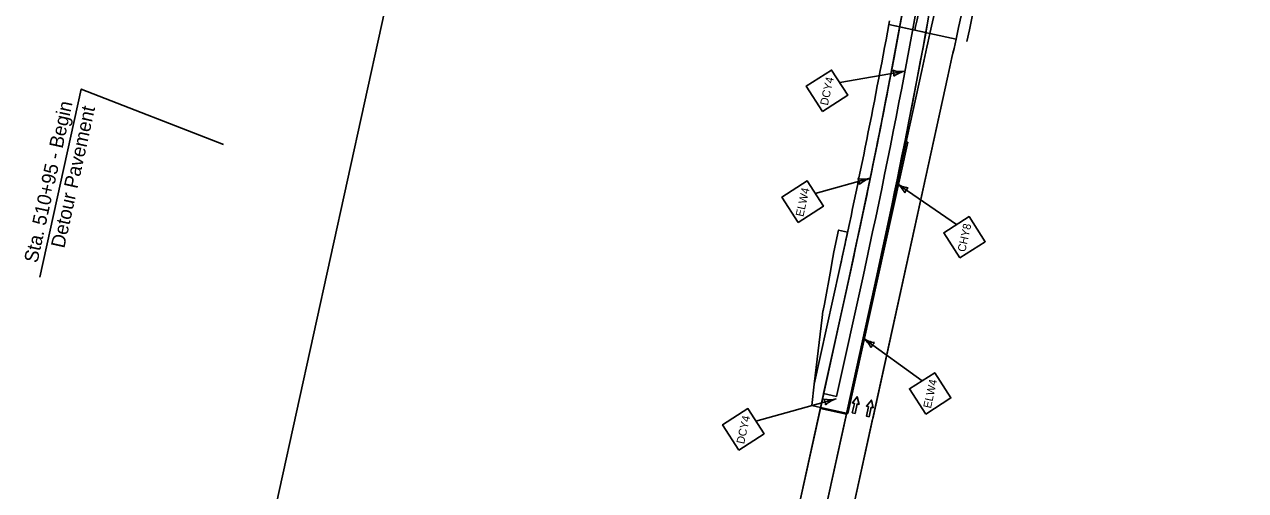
# Model space of a CAD drawing. Extents: x 14104283 to 14129344, y 8637090 to 8673339.
# Drawn here: x 14107065 to 14108164, y 8638989 to 8639409 of the extents above; entities that cross this region are included whole.
import ezdxf

# ---------------------------------------------------------------- set-up
doc = ezdxf.new("R2010")
doc.units = 0
for name, color, linetype in [('Cell', 7, 'Continuous'), ('Default', 7, 'Continuous'), ('dsn_stg_shd_prev', 7, 'Continuous'), ('dsnNonPlotable', 7, 'Continuous'), ('dsnPaintExistingEdgeLineRightWhite', 7, 'Continuous'), ('dsnPaintPlaceBrokenLineWhite', 7, 'Continuous'), ('dsnPaintPlaceChannelizingLaneYellow', 7, 'Continuous'), ('dsnPaintPlaceEdgeLineRightWhite', 7, 'Continuous'), ('dsnStdLabel', 7, 'Continuous'), ('dsnStgShadingPrevPav', 7, 'Continuous'), ('dsnTextOverlapOdd', 7, 'Continuous'), ('EdgePaved', 7, 'Continuous'), ('Level 2', 7, 'Continuous')]:
    doc.layers.add(name, color=color, linetype=linetype)

msp = doc.modelspace()

# ---------------------------------------------------------------- linework, layer by layer
at = {"layer": 'Cell'}
for points in [[(14107812.7, 8639058.7), (14107810.2, 8639059.2), (14107812.1, 8639067.7), (14107810.3, 8639068.1), (14107814.6, 8639073.6), (14107816.4, 8639066.8), (14107814.5, 8639067.2)], [(14107825.4, 8639055.7), (14107823, 8639056.2), (14107824.8, 8639064.8), (14107823, 8639065.2), (14107827.4, 8639070.6), (14107829.1, 8639063.8), (14107827.3, 8639064.2)]]:
    msp.add_lwpolyline(points, close=True, dxfattribs=at)
for points in [[(14107814.5, 8639067.2), (14107816.4, 8639066.8), (14107814.6, 8639073.6), (14107810.3, 8639068.1), (14107812.1, 8639067.7), (14107810.2, 8639059.2), (14107812.7, 8639058.7), (14107814.5, 8639067.2)], [(14107827.3, 8639064.2), (14107829.1, 8639063.8), (14107827.4, 8639070.6), (14107823, 8639065.2), (14107824.8, 8639064.8), (14107823, 8639056.2), (14107825.4, 8639055.7), (14107827.3, 8639064.2)]]:
    msp.add_lwpolyline(points, dxfattribs=at)
at = {"layer": 'Default'}
for p, q in [((14107880.1, 8639400.5), (14107903.6, 8639395.4)), ((14107880.1, 8639400.5), (14107903.6, 8639395.4)), ((14107678, 8638480.1), (14107872.9, 8639367.3)), ((14107896.3, 8639362.1), (14107701.4, 8638474.9)), ((14107808.3, 8639185.2), (14107781.5, 8639063.2)), ((14107784.4, 8639076.5), (14107808.5, 8639186)), ((14107820.2, 8639183.4), (14107796.1, 8639073.9)), ((14107805, 8639058.1), (14107831.8, 8639180.1)), ((14107796.1, 8639073.9), (14107784.4, 8639076.5)), ((14107678, 8638480.1), (14107804.9, 8639058.1)), ((14107781.5, 8639063.2), (14107752, 8638929.7)), ((14107781.5, 8639063.2), (14107805, 8639058.1)), ((14107804.9, 8639058.1), (14107781.5, 8639063.2))]:
    msp.add_line(p, q, dxfattribs=at)
for centre, radius, start, end in [((14089678.7, 8643364.1), 18628, 347.71493, 348.77604), ((14089678.7, 8643364.1), 18652, 347.71493, 348.77604), ((14101471.4, 8640577.3), 6488, 347.61021, 351.32599), ((14101471.6, 8640578.1), 6488, 347.61021, 351.32599), ((14101471.6, 8640578.1), 6500, 347.61021, 351.32599), ((14101471.4, 8640577.3), 6512, 348.21324, 351.32599), ((14089678.7, 8643364.1), 18628, 347.61021, 347.71493), ((14089678.7, 8643364.1), 18652, 347.61021, 347.71493), ((14101471.4, 8640577.3), 6512, 347.61021, 348.21324)]:
    msp.add_arc(centre, radius, start, end, dxfattribs=at)
at = {"layer": 'dsn_stg_shd_prev'}
msp.add_line((14107903.6, 8639395.4), (14107880.1, 8639400.5), dxfattribs=at)
for radius in [18628, 18662]:
    msp.add_arc((14089678.7, 8643364.1), radius, 347.71493, 348.77604, dxfattribs=at)
at = {"layer": 'dsnNonPlotable'}
msp.add_lwpolyline([(14107218.4, 8638642.3), (14107554.8, 8640173.3), (14108541.3, 8639956.6), (14108204.9, 8638425.6)], close=True, dxfattribs=at)
at = {"layer": 'dsnPaintExistingEdgeLineRightWhite'}
for p, q in [((14107468.8, 8637416), (14107828.5, 8639053.6)), ((14107781.7, 8639064), (14107752, 8638929.7))]:
    msp.add_line(p, q, dxfattribs=at)
at = {"layer": 'dsnPaintPlaceBrokenLineWhite'}
msp.add_line((14107796.1, 8639073.9), (14107820.2, 8639183.4), dxfattribs=at)
msp.add_arc((14101471.6, 8640578.1), 6500, 347.61021, 351.32599, dxfattribs=at)
at = {"layer": 'dsnPaintPlaceChannelizingLaneYellow'}
msp.add_arc((14101471.6, 8640578.1), 6512, 347.61021, 351.32599, dxfattribs=at)
at = {"layer": 'dsnPaintPlaceEdgeLineRightWhite'}
for p, q in [((14107808.5, 8639186), (14107781.7, 8639064)), ((14107807.9, 8639071.3), (14107831.9, 8639180.9))]:
    msp.add_line(p, q, dxfattribs=at)
msp.add_arc((14101471.6, 8640578.1), 6488, 347.61021, 351.32599, dxfattribs=at)
at = {"layer": 'dsnStdLabel'}
for p, q in [((14107798.9, 8639356.3), (14107857.9, 8639366.6)), ((14107777, 8639256.4), (14107826.4, 8639270.2)), ((14107904, 8639228.5), (14107850.2, 8639265.5)), ((14107873.1, 8639088), (14107820, 8639126.4)), ((14107723.6, 8639051.6), (14107795.8, 8639071.8))]:
    msp.add_line(p, q, dxfattribs=at)
for points in [[(14107783.4, 8639330.3), (14107806.2, 8639344.9), (14107791.6, 8639367.6), (14107768.9, 8639353.1)], [(14107761.5, 8639230.5), (14107784.2, 8639245.1), (14107769.7, 8639267.8), (14107746.9, 8639253.3)], [(14107907.1, 8639198.5), (14107929.9, 8639213.1), (14107915.3, 8639235.8), (14107892.6, 8639221.2)], [(14107876.3, 8639058), (14107899, 8639072.6), (14107884.5, 8639095.3), (14107861.7, 8639080.8)], [(14107708.1, 8639025.7), (14107730.9, 8639040.3), (14107716.3, 8639063), (14107693.6, 8639048.4)]]:
    msp.add_lwpolyline(points, close=True, dxfattribs=at)
for centre, radius, start, end in [((14107853.9, 8639389.2), 22.9, 251.8843, 279.9556), ((14107838.9, 8639363.3), 8.86, 352.2213, 27.6898), ((14107861.8, 8639344), 22.9, 99.9555, 128.0268), ((14107820.2, 8639292.3), 22.9, 257.5032, 285.5745), ((14107807.9, 8639265), 8.86, 357.8402, 33.3086), ((14107832.5, 8639248.1), 22.9, 105.5743, 133.6456), ((14107837.2, 8639246.6), 22.9, 27.4258, 55.4971), ((14107863.2, 8639284.4), 22.9, 235.4969, 263.5682), ((14107866.1, 8639254.6), 8.86, 127.7628, 163.2312), ((14107806.5, 8639107.8), 22.9, 26.1067, 54.178), ((14107833.4, 8639145), 22.9, 234.1779, 262.2491), ((14107835.6, 8639115.1), 8.86, 126.4437, 161.9122), ((14107789.7, 8639093.9), 22.9, 257.5032, 285.5745), ((14107777.3, 8639066.6), 8.86, 357.8402, 33.3086), ((14107802, 8639049.7), 22.9, 105.5743, 133.6456)]:
    msp.add_arc(centre, radius, start, end, dxfattribs=at)
at = {"layer": 'dsnStgShadingPrevPav'}
for p, q in [((14107843.1, 8639408.6), (14107852.9, 8639406.5)), ((14107866.5, 8639403.5), (14107852.9, 8639406.5)), ((14107880.1, 8639400.5), (14107866.5, 8639403.5)), ((14107866.5, 8639403.5), (14107866.5, 8639403.5)), ((14107858.7, 8639302.9), (14107872.9, 8639367.3)), ((14107806.3, 8639058.6), (14107860.2, 8639302.6)), ((14107860.2, 8639302.6), (14107858.7, 8639302.9)), ((14107808.5, 8639186), (14107781.7, 8639064)), ((14107781.7, 8639064), (14107806.3, 8639058.6))]:
    msp.add_line(p, q, dxfattribs=at)
for points in [[(14107867.2, 8639406.9), (14107866.5, 8639403.5), (14107876.4, 8639401.4), (14107866.5, 8639403.5), (14107843, 8639408.6), (14107843.8, 8639412)], [(14107867.2, 8639406.9), (14107866.5, 8639403.5), (14107880.1, 8639400.5)], [(14107798.7, 8639188.2), (14107776, 8639084.9), (14107783, 8639144.9), (14107783.8, 8639150.7), (14107783.9, 8639151.1), (14107785.2, 8639156.8), (14107790.8, 8639188), (14107791.7, 8639193.7), (14107793.6, 8639204.1), (14107797.9, 8639223.6), (14107806, 8639221.8)], [(14107808.5, 8639186), (14107781.7, 8639064), (14107773.8, 8639065.7), (14107776, 8639084.9), (14107798.7, 8639188.2)]]:
    msp.add_lwpolyline(points, dxfattribs=at)
for centre, radius, start, end in [((14089678.7, 8643364.1), 18628, 347.715, 348.77604), ((14098576.8, 8641447.8), 9512, 347.61021, 348.1762), ((14098576.8, 8641447.8), 9512, 347.61021, 348.1762), ((14101471.6, 8640578.1), 6478, 347.61021, 349.5995), ((14101471.6, 8640578.1), 6488, 347.61021, 349.59643), ((14101471.6, 8640578.1), 6488, 347.61021, 349.59643), ((14089678.7, 8643364.1), 18628, 347.61021, 347.715), ((14101471.6, 8640578.1), 6478, 347.61021, 347.88803), ((14101471.6, 8640578.1), 6478, 347.88803, 347.91481)]:
    msp.add_arc(centre, radius, start, end, dxfattribs=at)
at = {"layer": 'dsnTextOverlapOdd'}
msp.add_lwpolyline([(14107079.3, 8639181.3), (14107116.5, 8639350.5), (14107244.4, 8639300.7)], dxfattribs=at)
at = {"layer": 'EdgePaved'}
for p, q in [((14107872.9, 8639367.3), (14107678, 8638480.1)), ((14107828.6, 8639053.7), (14107896.3, 8639362.1))]:
    msp.add_line(p, q, dxfattribs=at)
for radius in [18628, 18652]:
    msp.add_arc((14089678.7, 8643364.1), radius, 347.61021, 347.71493, dxfattribs=at)

# ---------------------------------------------------------------- texts
at = {"layer": 'dsnStdLabel'}
for s, p in [('DCY4', (14107788.2, 8639335.3)), ('ELW4', (14107766.2, 8639235.2)), ('CHY8', (14107911.9, 8639203.5)), ('ELW4', (14107881, 8639062.8)), ('DCY4', (14107712.9, 8639030.7))]:
    msp.add_text(s, height=7.2, rotation=77.6078, dxfattribs=at).set_placement(p)
at = {"layer": 'Level 2'}
for s, p in [('Sta. 510+95 - Begin', (14107077, 8639193.4)), ('Detour Pavement', (14107101.2, 8639206.7))]:
    msp.add_text(s, height=12.5, rotation=77.6328, dxfattribs=at).set_placement(p)

doc.saveas('drawing.dxf')
